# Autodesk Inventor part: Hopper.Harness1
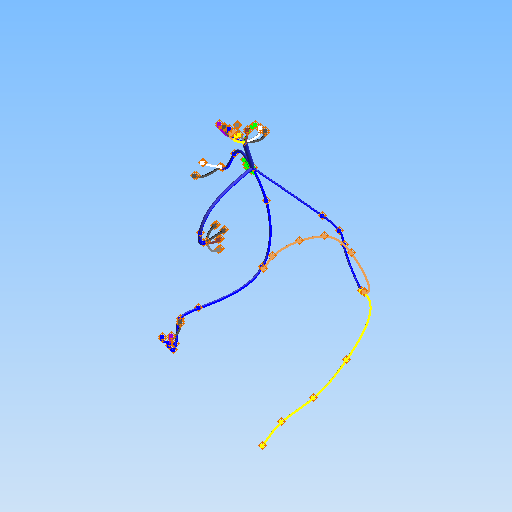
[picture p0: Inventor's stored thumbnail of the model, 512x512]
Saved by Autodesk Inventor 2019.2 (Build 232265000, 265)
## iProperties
GlobalPropertyList: <PropertyList/>
Key:2|1|1|0|4|0|0|0|18|0|0|0|Level:1: <CableProperty entityType="Connector" version="1.0"><ID editable="" value=""/><UserDefined/><Name editable="True" value=""/><Refdes editable="True" value="TERM1
Key:2|1|1|0|4|0|0|0|19|0|0|0|Level:1: <CableProperty entityType="Connector" version="1.0"><ID editable="" value=""/><UserDefined/><Name editable="True" value=""/><Refdes editable="True" value="TERM2
Key:2|1|1|0|4|0|0|0|20|0|0|0|Level:1: <CableProperty entityType="Connector" version="1.0"><ID editable="" value=""/><UserDefined/><Name editable="True" value=""/><Refdes editable="True" value="TERM3
Key:2|1|1|0|4|0|0|0|21|0|0|0|Level:1: <CableProperty entityType="Connector" version="1.0"><ID editable="" value=""/><UserDefined/><Name editable="True" value=""/><Refdes editable="True" value="TERM4
Key:2|1|1|0|4|0|0|0|22|0|0|0|Level:1: <CableProperty entityType="Connector" version="1.0"><ID editable="" value=""/><UserDefined/><Name editable="True" value=""/><Refdes editable="True" value="TERM5
Key:2|1|1|0|4|0|0|0|23|0|0|0|Level:1: <CableProperty entityType="Connector" version="1.0"><ID editable="" value=""/><UserDefined/><Name editable="True" value=""/><Refdes editable="True" value="TERM6
Key:2|1|1|0|4|0|0|0|24|0|0|0|Level:1: <CableProperty entityType="Connector" version="1.0"><ID editable="" value=""/><UserDefined/><Name editable="True" value=""/><Refdes editable="True" value="TERM7
Key:2|1|1|0|4|0|0|0|25|0|0|0|Level:1: <CableProperty entityType="Connector" version="1.0"><ID editable="" value=""/><UserDefined/><Name editable="True" value=""/><Refdes editable="True" value="TERM8
Key:2|1|1|0|4|0|0|0|26|0|0|0|Level:1: <CableProperty entityType="Connector" version="1.0"><ID editable="" value=""/><UserDefined/><Name editable="True" value=""/><Refdes editable="True" value="TERM9
Key:2|1|1|0|4|0|0|0|27|0|0|0|Level:1: <CableProperty entityType="Connector" version="1.0"><ID editable="" value=""/><UserDefined/><Name editable="True" value=""/><Refdes editable="True" value="TERM1
Key:2|1|1|0|4|0|0|0|28|0|0|0|Level:1: <CableProperty entityType="Connector" version="1.0"><ID editable="" value=""/><UserDefined/><Name editable="True" value=""/><Refdes editable="True" value="TERM1
Key:2|1|1|0|4|0|0|0|29|0|0|0|Level:1: <CableProperty entityType="Connector" version="1.0"><ID editable="" value=""/><UserDefined/><Name editable="True" value=""/><Refdes editable="True" value="TERM1
Key:2|1|1|0|4|0|0|0|30|0|0|0|Level:1: <CableProperty entityType="Connector" version="1.0"><ID editable="" value=""/><UserDefined/><Name editable="True" value=""/><Refdes editable="True" value="J1" o
Key:2|1|2|0|36|0|0|0|2|1|1|0|4|0|0|0|30|0|0|0|16|2|0|0|16|0|: <CableProperty entityType="ConnectorPin" version="1.0"><ID editable="" value=""/><UserDefined/><PinName editable="True" value="1"/><AttachedParts><AttachedPart 
Key:2|1|2|0|36|0|0|0|2|1|1|0|4|0|0|0|30|0|0|0|16|2|0|0|16|0|: <CableProperty entityType="ConnectorPin" version="1.0"><ID editable="" value=""/><UserDefined/><PinName editable="True" value="2"/><AttachedParts><AttachedPart 
Key:2|1|2|0|36|0|0|0|2|1|1|0|4|0|0|0|30|0|0|0|16|2|0|0|16|0|: <CableProperty entityType="ConnectorPin" version="1.0"><ID editable="" value=""/><UserDefined/><PinName editable="True" value="3"/><AttachedParts><AttachedPart 
Key:2|1|2|0|36|0|0|0|2|1|1|0|4|0|0|0|30|0|0|0|16|2|0|0|16|0|: <CableProperty entityType="ConnectorPin" version="1.0"><ID editable="" value=""/><UserDefined/><PinName editable="True" value="9"/><AttachedParts><AttachedPart 
Key:2|1|2|0|36|0|0|0|2|1|1|0|4|0|0|0|30|0|0|0|16|2|0|0|16|0|: <CableProperty entityType="ConnectorPin" version="1.0"><ID editable="" value=""/><UserDefined/><PinName editable="True" value="11"/><AttachedParts><AttachedPart
Key:2|1|2|0|36|0|0|0|2|1|1|0|4|0|0|0|30|0|0|0|16|2|0|0|16|0|: <CableProperty entityType="ConnectorPin" version="1.0"><ID editable="" value=""/><UserDefined/><PinName editable="True" value="19"/><AttachedParts><AttachedPart
Key:2|1|2|0|36|0|0|0|2|1|1|0|4|0|0|0|30|0|0|0|16|2|0|0|16|0|: <CableProperty entityType="ConnectorPin" version="1.0"><ID editable="" value=""/><UserDefined/><PinName editable="True" value="18"/><AttachedParts><AttachedPart
Key:2|1|2|0|36|0|0|0|2|1|1|0|4|0|0|0|30|0|0|0|16|2|0|0|16|0|: <CableProperty entityType="ConnectorPin" version="1.0"><ID editable="" value=""/><UserDefined/><PinName editable="True" value="17"/><AttachedParts><AttachedPart
Key:2|1|2|0|36|0|0|0|2|1|1|0|4|0|0|0|30|0|0|0|16|2|0|0|16|0|: <CableProperty entityType="ConnectorPin" version="1.0"><ID editable="" value=""/><UserDefined/><PinName editable="True" value="16"/><AttachedParts><AttachedPart
Key:2|1|2|0|36|0|0|0|2|1|1|0|4|0|0|0|30|0|0|0|16|2|0|0|16|0|: <CableProperty entityType="ConnectorPin" version="1.0"><ID editable="" value=""/><UserDefined/><PinName editable="True" value="15"/><AttachedParts><AttachedPart
Created: 2005-11
Part Number: Hopper.Harness1
Document SubType Name: Modeling
Designer: floress
Material: Default
Density: 1 g/cm^3
Appearance: Default
Author: floress
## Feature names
1. Sweep22
2. Sweep52
3. Sweep56
4. Sweep94
5. Sweep139
6. Sweep140
7. Sweep153
8. Sweep154
9. Sweep157
10. Sweep158
11. Sweep168
12. Sweep183
13. Sweep184
14. Sweep185
15. Sweep186
16. Sweep187
17. Sweep188
18. Sweep189
19. Sweep190
20. Sweep191
21. Sweep192
22. Sweep193
23. Sweep194
24. Sweep195
25. Sweep196
26. Sweep197
27. Sweep198
## Parameters: d21 = 0, d51 = 0, d55 = 0, d93 = 0, d138 = 0, d139 = 0, d152 = 0, d153 = 0, d156 = 0, d157 = 0, d167 = 0, d182 = 0, d183 = 0, d184 = 0, d185 = 0, d186 = 0, d187 = 0, d188 = 0, d189 = 0, d190 = 0, d191 = 0, d192 = 0, d193 = 0, d194 = 0, d195 = 0, d196 = 0, d197 = 0, d198 = 0, d199 = 0, d200 = 0, d201 = 0, d202 = 0, d203 = 0, d204 = 0, d205 = 0, d206 = 0, d207 = 0, d208 = 0, d209 = 0, d210 = 0, d211 = 0, d212 = 0, d213 = 0, d214 = 0, d215 = 0, d216 = 0, d217 = 0, d218 = 0, d219 = 0, d220 = 0, d221 = 0, d222 = 0, d223 = 0, d224 = 0
